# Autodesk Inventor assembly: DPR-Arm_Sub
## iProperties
Created: 2007-01
Part Number: DPR-Arm_Sub
Document SubType Name: Assembly
Designer: Administrator
Stock Number: DPR-Arm_Sub
Author: Administrator
